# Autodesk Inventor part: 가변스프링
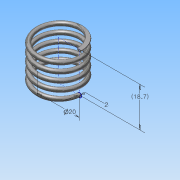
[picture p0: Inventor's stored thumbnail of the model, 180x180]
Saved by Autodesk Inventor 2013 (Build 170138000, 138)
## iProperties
Created: 2019-01
Part Number: 가변스프링
Material: 스테인리스강
Document SubType Name: Modeling
Designer: Gpr
Density: 8.08 g/cm^3
Mass: 7.81004 g
Surface Area: 19.6297 cm^2
Volume: 0.966589 cm^3
Author: Gpr
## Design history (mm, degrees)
sketch "스케치1"
  geometry: L1 (0, 0)-(10, 0); L2 (10, 0)-(10, 18.7); L3 (10, 18.7)-(0, 18.7); L4 (0, 18.7)-(0, 0); C1 r 1 at (10, 0)
  constraints: 8 end point, 2 parallel, 1 centre point, 1 coincident, 1 horizontal, 1 perpendicular
  dimensions: "d0" = 2 diameter of C1; "d1" = 20 diameter of L2 L4; "d2" = 18.7 distance between parallel lines of L3 L1 (derived)
feature "코일1" pitch "d3" = 10; turns "d5" = 5; dims "d4" = 18.7 (= d2), "d6" = 0, angle "d7" = 90 deg, angle "d8" = 90 deg, "d9" = 0, "d10" = 0
sketch "스케치2"
  geometry: L1 (-9, 0)-(-11, 0) reference; L2 (-9, 0)-(-11, 0) reference; 1 further point
  constraints: 2 horizontal alignment
extrude "돌출1" cut sketch "스케치2" stored distance "d11" = 10; taper "d12" = 0 deg
node "작업 평면1"
sketch "스케치3"
  geometry: L1 (9, 0)-(11, 0) reference; 1 further point
  constraints: 1 horizontal alignment
extrude "돌출2" cut sketch "스케치3" stored distance "d13" = 10; taper "d14" = 0 deg
node "솔리드1"
node "절단 모서리 투영1"
node "절단 모서리 투영2"
node "절단 모서리 투영3"
